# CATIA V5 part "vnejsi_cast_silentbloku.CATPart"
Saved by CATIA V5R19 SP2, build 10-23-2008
Part number: vnejsi_cast_silentbloku
Bounding box of the stored display mesh (mm): x -44.968 to 44.968, y -34 to 34, z -44.933 to 44.933
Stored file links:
  C:\Users\Martiin\Desktop\9.semestr\Projekt-diplomka\3D model\silentbloky\vnejsi_cast_silentbloku.CATPart
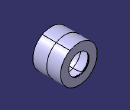
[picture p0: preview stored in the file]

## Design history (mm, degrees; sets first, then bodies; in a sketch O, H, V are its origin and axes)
Body1 (main body)
  Sketch1 on yz-plane, origin (0, 0, 0), H (0, 1, 0), V (0, 0, 1)
    axis line L1 (-49.7859, 0) -> (129.8264, 0)
    point P1 (-49.7859, 0)
    construction line L2 (0, 59.2551) -> (0, -50.8447)
    point P3 (0, 59.2551)
    line L3 (-34, 45) -> (0, 45)
    line L4 (-34, 45) -> (-34, 25)
    point P5 (-34, 45)
    arc A1 centre (0, 0) radius 40 from (0, 40) to (-30.3575, 26.0465) ccw
    point P6 (0, 40)
    point P7 (0, 45)
    line L5 (-34, 25) -> (-32.6343, 25)
    arc A2 centre (-32.6343, 28) radius 3 from (-30.3575, 26.0465) to (-32.6343, 25) cw
    point P8 (-30.3575, 26.0465)
    point P9 (-32.6343, 25)
    point P11 (-34, 25)
    point P12 (34, 45)
    point P13 (30.3575, 26.0465)
    point P14 (32.6343, 25)
    point P16 (34, 25)
    line L6 (34, 45) -> (34, 25)
    line L7 (34, 25) -> (32.6343, 25)
    arc A3 centre (32.6343, 28) radius 3 from (30.3575, 26.0465) to (32.6343, 25) ccw
    point P17 (0, 45)
    line L8 (34, 45) -> (0, 45)
    point P18 (0, 40)
    arc A4 centre (0, 0) radius 40 from (0, 40) to (30.3575, 26.0465) cw
    distance L3 L1 = 45
    distance L4 L2 = 34
    radius A1 = 40
    distance L5 L1 = 25
    radius A2 = 3
    coincidence: P1 H, P3 V, L2 P6, L2 P7, P6 P18, P7 P17
    horizontal: L1 H, L3 H, L5 H
    vertical: L2 V, L4 V
    tangency: A2 A1, A2 L5
    symmetry: P5 P12 L2, P8 P13 L2, P9 P14 L2, P11 P16 L2, L4 L6 L2, L5 L7 L2, A2 A3 L2, P7 P17 L2, L3 L8 L2, P6 P18 L2, A1 A4 L2
  Shaft1: profile Sketch1, axis Sketch1.L1, angle 360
